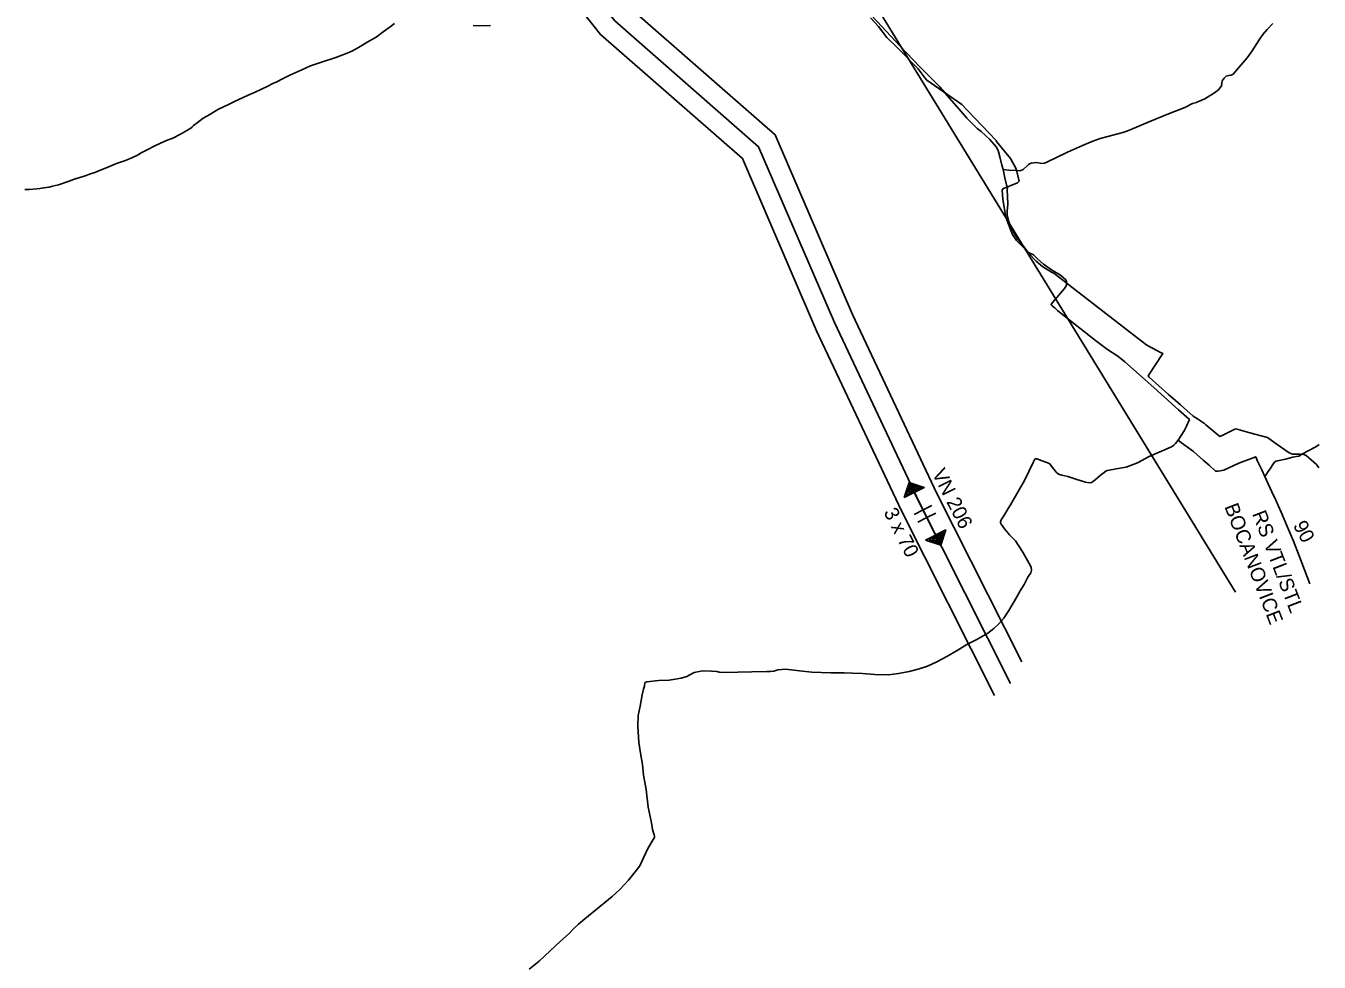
# Model space of a CAD drawing. Extents: x -444841 to -429627, y -1134006 to -1129851.
# Drawn here: x -441903 to -441182, y -1132365 to -1131843 of the extents above; entities that cross this region are included whole.
import ezdxf

# ---------------------------------------------------------------- set-up
doc = ezdxf.new("R2010")
doc.units = 0
for name, color, linetype in [('Vrstva 10', 7, 'Continuous'), ('Vrstva 13', 7, 'Continuous'), ('Vrstva 15', 7, 'Continuous'), ('Vrstva 27', 7, 'Continuous'), ('Vrstva 29', 7, 'Continuous'), ('Vrstva 30', 7, 'Continuous'), ('Vrstva 58', 7, 'Continuous'), ('Vrstva 59', 7, 'Continuous')]:
    doc.layers.add(name, color=color, linetype=linetype)

msp = doc.modelspace()

# ---------------------------------------------------------------- linework, layer by layer
at = {"layer": 'Vrstva 10'}
for p, q in [((-441402.8, -1132112.7), (-441397.8, -1132110.18)), ((-441407.8, -1132115.22), (-441402.8, -1132112.7)), ((-441405.66, -1132119.47), (-441400.66, -1132116.95)), ((-441400.66, -1132116.95), (-441395.66, -1132114.43))]:
    msp.add_line(p, q, dxfattribs=at)
for points in [[(-441640.89, -1131756.15), (-441574.87, -1131839.72), (-441494.51, -1131910), (-441452.12, -1132008.18), (-441404.98, -1132108.37), (-441353.98, -1132209.5)], [(-441395.74, -1132126.7), (-441401.73, -1132114.82), (-441407.72, -1132102.95)]]:
    msp.add_lwpolyline(points, dxfattribs=at)
for points in [[(-441413.34, -1132105.78), (-441410.55, -1132097.32), (-441402.09, -1132100.11)], [(-441412.15, -1132104.4), (-441410.11, -1132098.21), (-441403.92, -1132100.25)], [(-441410.96, -1132103.01), (-441409.66, -1132099.09), (-441405.74, -1132100.38)], [(-441409.76, -1132101.63), (-441409.22, -1132099.98), (-441407.56, -1132100.52)], [(-441401.36, -1132129.54), (-441390.11, -1132123.86), (-441392.9, -1132132.32)], [(-441399.54, -1132129.4), (-441391.31, -1132125.25), (-441393.35, -1132131.44)], [(-441397.72, -1132129.26), (-441392.5, -1132126.63), (-441393.79, -1132130.56)], [(-441395.89, -1132129.13), (-441393.7, -1132128.02), (-441394.24, -1132129.67)]]:
    msp.add_lwpolyline(points, close=True, dxfattribs=at)
at = {"layer": 'Vrstva 15'}
for points in [[(-441649.52, -1131762.97), (-441582.87, -1131847.33), (-441503.62, -1131916.64), (-441462.15, -1132012.71), (-441414.87, -1132113.19), (-441362.91, -1132216.23)], [(-441347.71, -1132197.5), (-441395.09, -1132103.55), (-441442.09, -1132003.66), (-441485.39, -1131903.36), (-441566.87, -1131832.11), (-441625.25, -1131758.2)]]:
    msp.add_lwpolyline(points, dxfattribs=at)
at = {"layer": 'Vrstva 27'}
for points in [[(-441358.13, -1131922.69), (-441358.79, -1131920.35), (-441359.9, -1131915.58), (-441360.88, -1131912.03), (-441361.98, -1131910.11), (-441365.48, -1131906.04), (-441370.4, -1131901.57), (-441372.5, -1131899.8), (-441378.42, -1131894.03), (-441380.23, -1131891.81), (-441389.51, -1131881.32), (-441391.67, -1131878.48), (-441392.57, -1131877.6), (-441393.49, -1131876.52), (-441394.31, -1131875.72), (-441396.91, -1131873.09), (-441404.5, -1131865.38), (-441415.65, -1131853.65), (-441428.33, -1131840.06), (-441439.82, -1131827.89), (-441446.05, -1131820.66)], [(-441697.71, -1131841.22), (-441700.24, -1131843.05), (-441704.09, -1131845.96), (-441708.05, -1131848.84), (-441712.67, -1131851.56)], [(-441644.14, -1131842.32), (-441650.08, -1131842.58), (-441653.81, -1131842.37)], [(-441210.73, -1131844.53), (-441207.65, -1131841.26)], [(-441250, -1131885.19), (-441245.6, -1131883.27), (-441240.07, -1131879.87), (-441237.67, -1131878.03), (-441236.15, -1131876.07), (-441236.02, -1131874.27), (-441235.86, -1131873.3), (-441234.73, -1131871.76), (-441233.68, -1131870.59), (-441232.1, -1131870.29), (-441230.75, -1131870.03), (-441229.65, -1131869.59), (-441226.6, -1131865.82), (-441221.92, -1131860.38), (-441219.05, -1131856.56), (-441215.19, -1131850.39), (-441213.15, -1131847.38), (-441210.73, -1131844.53)], [(-441875, -1131927.67), (-441869.75, -1131926.05), (-441867.89, -1131925.4), (-441865.01, -1131924.31), (-441862.4, -1131923.32), (-441859.88, -1131922.32), (-441856.86, -1131921.13), (-441852.82, -1131919.46), (-441847.87, -1131917.74), (-441844.4, -1131916.28), (-441840.81, -1131914.45), (-441839.41, -1131913.62), (-441835.84, -1131911.74), (-441831.41, -1131909.53), (-441828.77, -1131908.18), (-441825.02, -1131906.55), (-441821.53, -1131905.26), (-441817.17, -1131903.05), (-441813.24, -1131900.85), (-441810.91, -1131899.22), (-441810.59, -1131898.98), (-441809.88, -1131898.1), (-441807.88, -1131896.6), (-441804.44, -1131894.11), (-441802.14, -1131892.73), (-441795.87, -1131889.1), (-441790.46, -1131886.42), (-441786.58, -1131884.62), (-441782.27, -1131882.58), (-441779.42, -1131881.29), (-441775.47, -1131879.49), (-441772.41, -1131877.99), (-441768.49, -1131876.15), (-441765.58, -1131874.69), (-441763.43, -1131873.71), (-441760.19, -1131872.06), (-441756.2, -1131870.05), (-441749.53, -1131867.03), (-441744.56, -1131864.94), (-441738.43, -1131862.86), (-441730.56, -1131860.18), (-441724.24, -1131857.76), (-441721.62, -1131856.69), (-441717.82, -1131854.67), (-441712.67, -1131851.56)], [(-441256.36, -1131887.88), (-441252.41, -1131885.91), (-441250.2, -1131885.28), (-441250, -1131885.19)], [(-441358.13, -1131922.69), (-441354.92, -1131923.14), (-441351.08, -1131923.27), (-441348.51, -1131923.55), (-441346.86, -1131922.76), (-441344.55, -1131920.44), (-441343.84, -1131919.97), (-441343.07, -1131919.39), (-441342.48, -1131919.12), (-441341.16, -1131918.91), (-441339.46, -1131918.87), (-441336.4, -1131919.34), (-441334.98, -1131919.16), (-441333.61, -1131918.55), (-441322.23, -1131913.07), (-441313.82, -1131909.29), (-441312.44, -1131908.72), (-441307.93, -1131906.86), (-441304, -1131905.38), (-441299.7, -1131904.32), (-441294.74, -1131903.09), (-441291.2, -1131902.06), (-441289.07, -1131901.39), (-441283.58, -1131899.04), (-441277.2, -1131896.27), (-441264.78, -1131891.22), (-441258.49, -1131888.94), (-441256.36, -1131887.88)], [(-441358.13, -1131922.69), (-441357.53, -1131925.58), (-441357.16, -1131927.39), (-441356.14, -1131931.35), (-441355.68, -1131933.13)], [(-441904.06, -1131933.9), (-441901.53, -1131933.83), (-441897.38, -1131933.48), (-441895.62, -1131933.32), (-441893.43, -1131933.03), (-441890.54, -1131932.51), (-441888.6, -1131932.1), (-441885.31, -1131931.25), (-441879.9, -1131929.41), (-441875.39, -1131927.79), (-441875, -1131927.67)], [(-441355.68, -1131933.13), (-441355.76, -1131933.81), (-441355.92, -1131934.32), (-441355.64, -1131937.61), (-441355.52, -1131942.17), (-441355.76, -1131945.82), (-441355.79, -1131947.95), (-441354.98, -1131951.96), (-441354.1, -1131953.73), (-441351.35, -1131959.24), (-441349.91, -1131961.59), (-441348.88, -1131962.77), (-441346.74, -1131965.52), (-441344.23, -1131968.84), (-441341.18, -1131970.39), (-441338.66, -1131972.82), (-441335.56, -1131975.54), (-441331.15, -1131978.74), (-441326.09, -1131981.69), (-441323.15, -1131984.2), (-441322.75, -1131985.18), (-441322.59, -1131986.43), (-441323.02, -1131988.01), (-441323.8, -1131989.11), (-441330.4, -1131996.77), (-441331.05, -1131997.7), (-441331.35, -1131998.21), (-441330.72, -1131998.73), (-441329.59, -1131999.7), (-441329.27, -1132000)], [(-441329.27, -1132000), (-441327.5, -1132001.68), (-441306.62, -1132018.15), (-441299.84, -1132023.08), (-441294.15, -1132026.93), (-441290.22, -1132030.08), (-441273.9, -1132044.31), (-441260.29, -1132056.8), (-441254.16, -1132062.27), (-441255.73, -1132065.89), (-441257.09, -1132068.48), (-441260.39, -1132073.78)], [(-441295.08, -1132089.84), (-441289.5, -1132088.74), (-441283.11, -1132086.37), (-441276.65, -1132082.86), (-441264.16, -1132077.52), (-441262.83, -1132076.61), (-441261.84, -1132075.71), (-441260.39, -1132073.78)], [(-441250, -1132081.78), (-441251.91, -1132080.14), (-441258.62, -1132075.27), (-441260.39, -1132073.78)], [(-441216.04, -1132085.44), (-441217.12, -1132083.03), (-441226.47, -1132086.51), (-441234.89, -1132090.45), (-441238.12, -1132090.98), (-441239.51, -1132091.04), (-441243.14, -1132087.7), (-441246.36, -1132084.92), (-441250, -1132081.78)], [(-441211.96, -1132093.97), (-441211.53, -1132093.3), (-441210.48, -1132091.85), (-441208.86, -1132089.35), (-441207.59, -1132087.31), (-441206.78, -1132086.25), (-441205.94, -1132085.54), (-441204.97, -1132085.29), (-441200.59, -1132084.28), (-441196.4, -1132083.28), (-441194.43, -1132082.94), (-441193.06, -1132082.72), (-441192.24, -1132082.34), (-441191.32, -1132081.64), (-441183.6, -1132077.44), (-441181.73, -1132076.13)], [(-441554.47, -1132286.43), (-441556.1, -1132278.5), (-441557.37, -1132268.68), (-441558.74, -1132260.75), (-441559.41, -1132254.77), (-441560.32, -1132249.46), (-441561.35, -1132242.44), (-441561.97, -1132233.44), (-441561.78, -1132227.48), (-441560.73, -1132222.14), (-441559.58, -1132215.91), (-441558.82, -1132212.64), (-441558.3, -1132210.95), (-441557.99, -1132209.23), (-441557.76, -1132208.91), (-441556.84, -1132208.67), (-441550.49, -1132207.95), (-441544.5, -1132207.61), (-441537.7, -1132206.58), (-441534.57, -1132205.74), (-441532.96, -1132204.78), (-441530.59, -1132203.49), (-441527.7, -1132202.86), (-441525.63, -1132202.53), (-441520.78, -1132202.7), (-441517.79, -1132202.91), (-441516.63, -1132203.15), (-441516.13, -1132203.32), (-441515.39, -1132203.33), (-441506.05, -1132203.21), (-441498.28, -1132203.05), (-441489.92, -1132202.9), (-441487.91, -1132202.83), (-441486.06, -1132202.71), (-441483.8, -1132201.84), (-441479.52, -1132201.58), (-441471.65, -1132202.47), (-441464.75, -1132203.19), (-441454.22, -1132203.65), (-441446.86, -1132203.6), (-441442.21, -1132203.83), (-441436.55, -1132204.05), (-441429.62, -1132204.57), (-441422.1, -1132204.68), (-441416.43, -1132204.04), (-441410.55, -1132202.93), (-441405.55, -1132201.64), (-441400.3, -1132199.81), (-441395.07, -1132197.44), (-441389.45, -1132194.48), (-441383.77, -1132191.09), (-441378.28, -1132187.8), (-441372.73, -1132184.92), (-441366.69, -1132181.41), (-441363.24, -1132178.85), (-441360.43, -1132176.23), (-441357.7, -1132173.05), (-441354.95, -1132168.82), (-441350.69, -1132161.58), (-441348.49, -1132157.88), (-441346.42, -1132154.39), (-441344.27, -1132150.26), (-441342.69, -1132147.86), (-441342.32, -1132146.28), (-441342.49, -1132144.67), (-441343.6, -1132142.53), (-441347.16, -1132136.19), (-441351.13, -1132130.02), (-441354.51, -1132126.51), (-441357.31, -1132123.15), (-441359.13, -1132120.61), (-441359.48, -1132119.97), (-441359.54, -1132119.4), (-441359.09, -1132118.27), (-441357.64, -1132115.99), (-441355.26, -1132111.89), (-441353.97, -1132109.84), (-441353.21, -1132108.53), (-441346.14, -1132096.21), (-441341.3, -1132086.26), (-441340.3, -1132084.37), (-441340.01, -1132084.15), (-441339.34, -1132084.26), (-441336.26, -1132085.24), (-441332.71, -1132086.65), (-441332.09, -1132087), (-441331.01, -1132088.36), (-441328.4, -1132091.63), (-441327.26, -1132092.76), (-441325.29, -1132093.3), (-441321.94, -1132093.97), (-441317.52, -1132095.45), (-441312.14, -1132097.17), (-441310.12, -1132097.49), (-441308.8, -1132097.43), (-441307.69, -1132096.61), (-441302.94, -1132092.71), (-441301.75, -1132091.73), (-441300.55, -1132090.87), (-441299.89, -1132090.64), (-441295.08, -1132089.84)], [(-441186.88, -1132153.92), (-441189.93, -1132146.16), (-441192.87, -1132138.22), (-441196.05, -1132130.11), (-441200.02, -1132120.92), (-441202.94, -1132113.92), (-441204.58, -1132110.25), (-441205.94, -1132107.26), (-441208.16, -1132102.55), (-441211.05, -1132096.02), (-441211.96, -1132093.97), (-441213.63, -1132090.27), (-441216.04, -1132085.44)], [(-441622.64, -1132368.96), (-441616.93, -1132364.46), (-441610.88, -1132358.8), (-441605.11, -1132353.39), (-441600.3, -1132349.05), (-441597.71, -1132346.29), (-441595.14, -1132343.95), (-441591.52, -1132340.84), (-441582.46, -1132333.42), (-441576.2, -1132328.5), (-441572, -1132324.45), (-441567.12, -1132319.26), (-441563.5, -1132314.6), (-441560.84, -1132311.28), (-441558.84, -1132306.9), (-441556.4, -1132301.71), (-441553.34, -1132296.6), (-441552.67, -1132295.41), (-441552.61, -1132294.7), (-441552.88, -1132293.93), (-441553.84, -1132291.07), (-441554.11, -1132288.4), (-441554.47, -1132286.43)]]:
    msp.add_lwpolyline(points, dxfattribs=at)
at = {"layer": 'Vrstva 58'}
msp.add_lwpolyline([(-441432.15, -1131838.08), (-441427.71, -1131842.93), (-441422.92, -1131849), (-441417.2, -1131854.58), (-441405.44, -1131866.62), (-441402.28, -1131870.8), (-441401.85, -1131871.61), (-441400.63, -1131872.95), (-441381.21, -1131886.47), (-441377.89, -1131889.75), (-441362.06, -1131906.6), (-441361.76, -1131907.03), (-441354.05, -1131916.59), (-441350.84, -1131922.38), (-441349.16, -1131929.28), (-441350.04, -1131930.19), (-441358.27, -1131933.58), (-441358.62, -1131934.44), (-441358.41, -1131936.74), (-441358.24, -1131939.5), (-441356.49, -1131949.24), (-441353.69, -1131957.19), (-441352.86, -1131959.02), (-441350.64, -1131962.3), (-441346.93, -1131966.02), (-441343.79, -1131969.58), (-441339.7, -1131973.9), (-441335.89, -1131976.97), (-441330.71, -1131980.11), (-441329.83, -1131980.51), (-441319.72, -1131988.4), (-441283.43, -1132016.38), (-441277.89, -1132020.72), (-441271.85, -1132023.9), (-441270.35, -1132024.9), (-441269, -1132025.36), (-441277.13, -1132037.83), (-441276.57, -1132038.65), (-441265.76, -1132048.29), (-441259.14, -1132054.04), (-441252.08, -1132060.36), (-441249.69, -1132061.94), (-441245.62, -1132064.49), (-441244.92, -1132065.16), (-441237.19, -1132071.74), (-441235.76, -1132071.22), (-441228.76, -1132067.59), (-441228.17, -1132067.35), (-441220.47, -1132069.64), (-441210.6, -1132072.2), (-441206.39, -1132075.28), (-441198.54, -1132080.74), (-441196.67, -1132081.53), (-441194.87, -1132081.56), (-441192.34, -1132081.66), (-441190.34, -1132081.81), (-441189.04, -1132082.37), (-441183.24, -1132087.41), (-441181.9, -1132089.24)], dxfattribs=at)
at = {"layer": 'Vrstva 59'}
msp.add_lwpolyline([(-441228.43, -1132158.56), (-441459.69, -1131781.27), (-441291.98, -1131581.6)], dxfattribs=at)

# ---------------------------------------------------------------- texts
at = {"layer": 'Vrstva 13'}
for s, p in [('VN 206', (-441397.95, -1132092.17)), ('3 x 70', (-441424.94, -1132113.92))]:
    msp.add_text(s, height=8, rotation=296.76186, dxfattribs=at).set_placement(p)
at = {"layer": 'Vrstva 29'}
for s, p in [('BOCANOVICE', (-441234.72, -1132110.8)), (' RS VTL/STL', (-441220.3, -1132112.05))]:
    msp.add_text(s, height=8, rotation=291.10484, dxfattribs=at).set_placement(p)
at = {"layer": 'Vrstva 30'}
msp.add_text('90', height=8, rotation=298.08937, dxfattribs=at).set_placement((-441196.46, -1132121.27))

doc.saveas('drawing.dxf')
